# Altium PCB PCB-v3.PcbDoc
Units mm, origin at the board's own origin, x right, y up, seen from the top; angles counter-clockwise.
Board outline 31.7 x 33.1 mm, 2 copper layers (Top Layer, Bottom Layer); 47 components, 31 nets, 206 pads, 13 vias.
Unrouted connection lines stored in the file: 46.
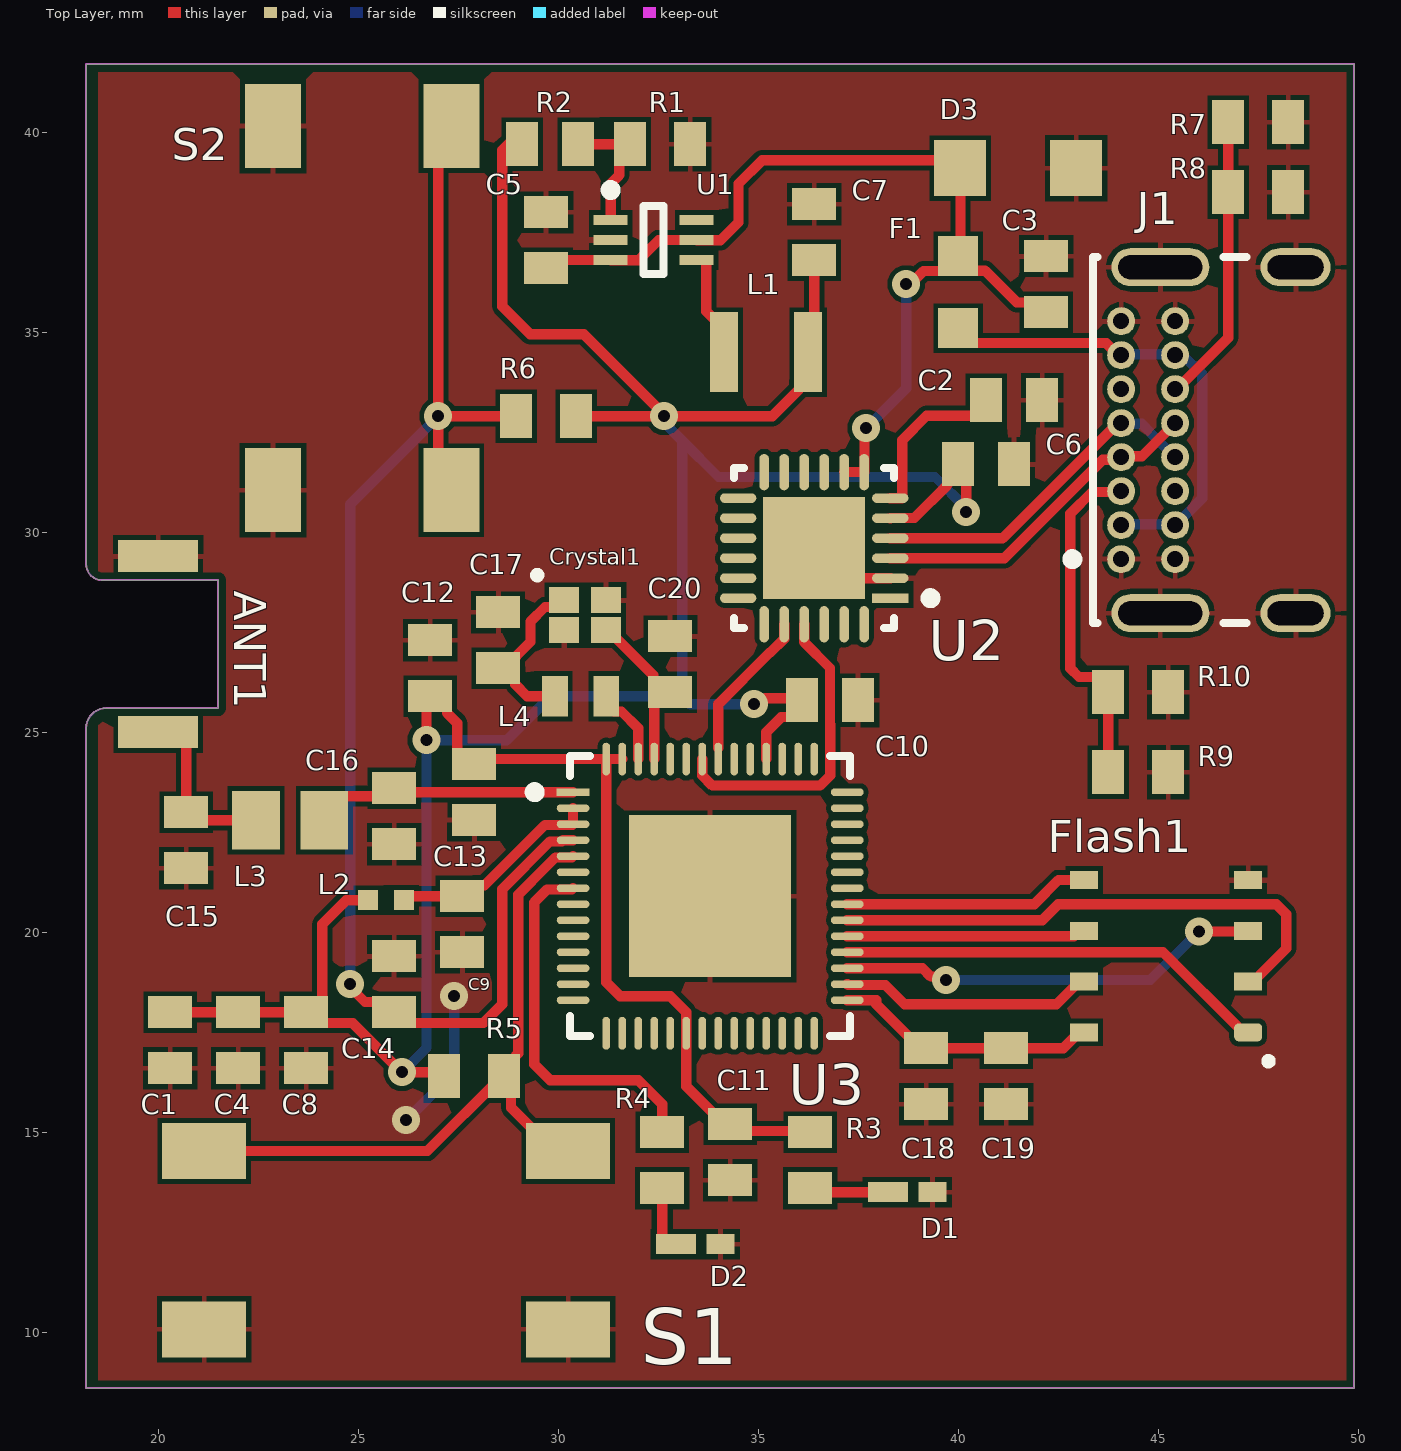
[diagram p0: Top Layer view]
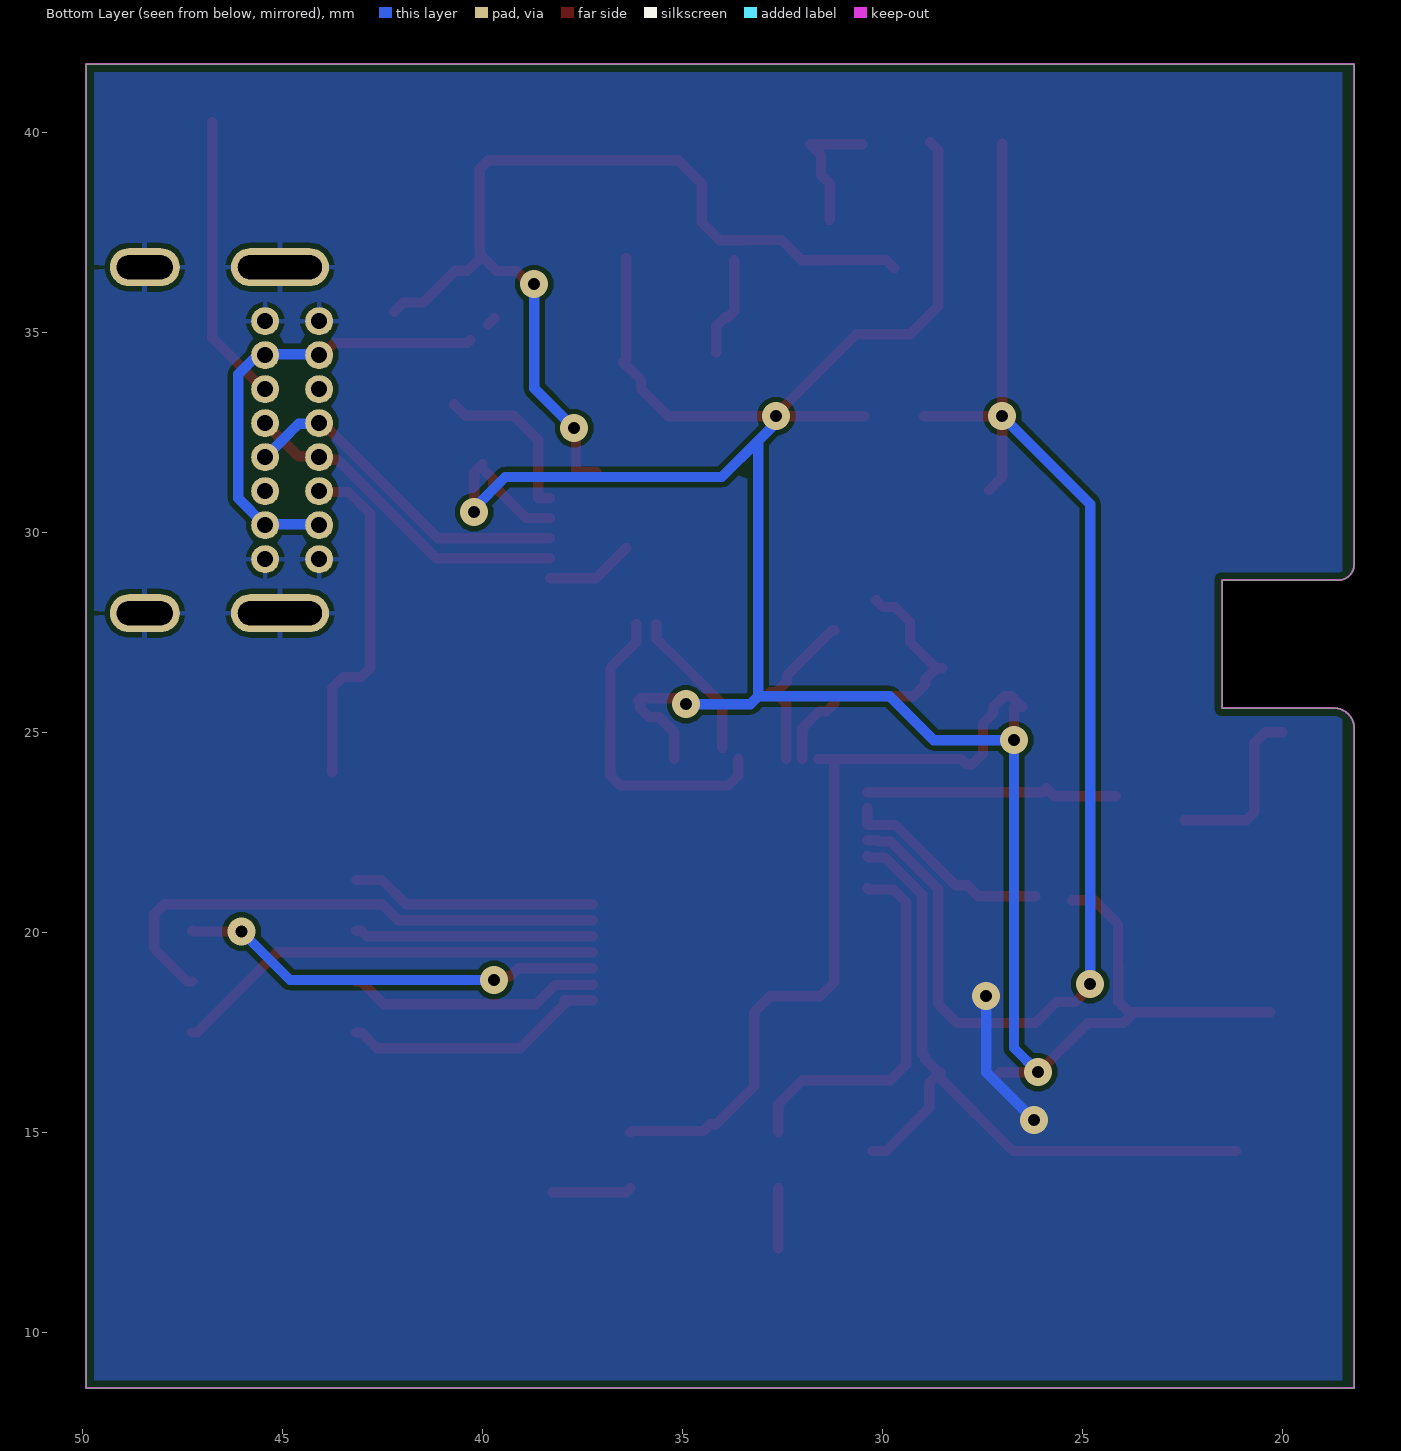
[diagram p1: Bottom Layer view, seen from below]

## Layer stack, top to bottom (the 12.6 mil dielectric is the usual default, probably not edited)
Top Solder: solder mask 0.0102, Solder Resist, Dk 3.5
Top Layer: signal copper 0.0356
Dielectric 1: dielectric 0.32, FR-4, Dk 4.8
Bottom Layer: signal copper 0.0356
Bottom Solder: solder mask 0.0102, Solder Resist, Dk 3.5

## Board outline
18.2,25.1 cw(c18.7,25.1) 18.7,25.6 21.5,25.6 21.5,28.8 18.6,28.8 cw(c18.6,29.2) 18.2,29.2 18.2,41.7 49.9,41.7 49.9,8.6 18.2,8.6

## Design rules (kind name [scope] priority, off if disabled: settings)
BoardOutlineClearance [All] p1: gap=0.2 ignorepadtopadclearanceinfootprint=FALSE
Clearance [All] p1: gap=0.127 ignorepadtopadclearanceinfootprint=TRUE except(0.254: Arc-Hole Track-Hole SMDPad-Hole THPad-Hole Via-Hole Fill-Hole Poly-Hole Region-Hole Text-Hole)
ComponentClearance [All] p1: gap=0.127 collisioncheckmode=3 verticalgap=0.127 showdistances=TRUE
DiffPairsRouting [All] p1: maxlimit=0.254 minlimit=0.127 mostfreqgap=0.127 toplayer_minwidth=0.127 toplayer_maxwidth=25.4 toplayer_prefwidth=0.127 bottomlayer_minwidth=0.127 bottomlayer_maxwidth=25.4 bottomlayer_prefwidth=0.127 maxuncoupledlength=12.7
Height [All] p1: minheight=0 maxheight=1816.048 prefheight=12.7
HoleSize [All] p1: absolutevalues=TRUE maxlimit=6.3 minlimit=0.3 maxpercent=80.000 minpercent=20.000
HoleToHoleClearance [All] p1: gap=0.254 allowstackedmicrovias=FALSE
MinimumAnnularRing [All] p1: minimumring=0.152
MinimumSolderMaskSliver [All] p1: minsoldermaskwidth=0.152
PlaneClearance [All] p1: clearance=0.127
PlaneConnect PlaneConnectPowerPads [InPadClass('PowerPads')] p1: planeconnectstyle=Direct reliefexpansion=0.508 reliefentries=4 reliefconductorwidth=0.254 reliefairgap=0.254
PlaneConnect [All] p2: pad.planeconnectstyle=Relief pad.reliefexpansion=0.3 pad.reliefentries=4 pad.reliefconductorwidth=0.127 pad.reliefairgap=0.127 via.planeconnectstyle=Direct via.reliefexpansion=0.3 via.reliefentries=4 via.reliefconductorwidth=0.127 via.reliefairgap=0.127
PolygonConnect PolygonConnectPowerPads [All vs (InPadClass('PowerPads'))] p1: connectstyle=Direct reliefconductorwidth=0.254 reliefentries=4 polygonreliefangle="90 Angle" airgapwidth=0.254
PolygonConnect [All] p2: thpad.connectstyle=Relief thpad.reliefconductorwidth=0.127 thpad.reliefentries=4 thpad.polygonreliefangle="90 Angle" thpad.airgapwidth=0.127 smdpad.connectstyle=Relief smdpad.reliefconductorwidth=0.127 smdpad.reliefentries=4 smdpad.polygonreliefangle="90 Angle" smdpad.airgapwidth=0.127 via.connectstyle=Direct via.reliefconductorwidth=0.127 via.reliefentries=4 via.polygonreliefangle="90 Angle" via.airgapwidth=0.127
RoutingVias [All] p1: holewidth=0.3 width=0.6 viastyle="Through Hole" minholewidth=0.3 minwidth=0.6 maxholewidth=0.6 maxwidth=6.6
SilkToSilkClearance [All] p1: silktosilkclearance=0.127
SilkToSolderMaskClearance [IsPad] p1: minsilkscreentomaskgap=0.127 clearancetoexposedcopper=TRUE
SolderMaskExpansion [All] p1: expansion=0.051 istentingtop=FALSE
SupplyNets "Schematic Supply Nets_4" [InNet('+3.3V')] p1: voltage=0.000
SupplyNets "Schematic Supply Nets_1" [InNet('GND')] p2: voltage=0.000
UnRoutedNet [All] p1: checkbadconnections=TRUE
Width Width_10mil [All] p1: maxlimit=25.4 minlimit=0.254 preferedwidth=0.254 minimp=50.000000 maximp=50.000000 favimp=50.000000
Width Width_6mil [All] p2: maxlimit=25.4 minlimit=0.152 preferedwidth=0.152 minimp=50.000000 maximp=50.000000 favimp=50.000000
Width Power_20mil [All] p3: maxlimit=25.4 minlimit=0.508 preferedwidth=0.508 minimp=50.000000 maximp=50.000000 favimp=50.000000
Width Power_12mil [All] p4: maxlimit=25.4 minlimit=0.305 preferedwidth=0.305 minimp=50.000000 maximp=50.000000 favimp=50.000000
Width Width_5mil [All] p5: maxlimit=25.4 minlimit=0.127 preferedwidth=0.127 minimp=50.000000 maximp=50.000000 favimp=50.000000
19 further rules are at their usual default settings.

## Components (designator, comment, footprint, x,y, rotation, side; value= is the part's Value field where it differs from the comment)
ANT1 "PCB_ANT" "Antenne // RFANT5220110A0T" 20,27.2 r90 top
C1 "10µF" CAP_General_0603 20.3,17.3 r90 top
C2 "1µF" CAP_General_0603 41.4,33.3 r0 top
C3 "10pF" CAP_General_0603 42.2,36.2 r270 top
C4 "1µF" CAP_General_0603 22,17.3 r90 top
C5 "4.7µF" CAP_General_0603 29.7,37.3 r270 top
C6 "1µF" CAP_General_0603 40.7,31.7 r0 top
C7 "1µF" CAP_General_0603 36.4,37.5 r270 top
C8 "0.1µF" CAP_General_0603 23.7,17.3 r90 top
C9 "0.1µF" CAP_General_0603 27.6,20.2 r90 top
C10 "0.1µF" CAP_General_0603 36.8,25.8 r0 top
C11 "0.1µF" CAP_General_0603 34.3,14.5 r90 top
C12 "1µF" CAP_General_0603 26.8,26.6 r270 top
C13 "10nF" CAP_General_0603 27.9,23.5 r90 top
C14 "0.1µF" CAP_General_0603 25.9,18.7 r270 top
C15 "1pF" CAP_General_0603 20.7,22.3 r90 top
C16 "1pF" CAP_General_0603 25.9,22.9 r90 top
C17 "10pF" CAP_General_0603 28.5,27.3 r90 top
C18 "0.1µF" CAP_General_0603 39.2,16.4 r90 top
C19 "10µF" CAP_General_0603 41.2,16.4 r90 top
C20 "10pF" CAP_General_0603 32.8,26.7 r90 top
Crystal1 "Crystal" "Crystal // ECS­400­8­47B2­CKM­TR" 30.675,27.925 r0 top
D1 "LED" "LED // KRDELPS1.22-UIVG-46-H3Q4-XX" 38.8,13.5 r0 top
D2 "LED" "LED // KRDELPS1.22-UIVG-46-H3Q4-XX" 33.5,12.2 r0 top
D3 "ESD diode 5V" "ESD diode 5V // SMF5.0A" 41.5,39.1 r0 top
F1 "Fuse" "Fuse // 0603L050SLYR" 40,36 r90 top
Flash1 "128 Mbit NOR Flash" "128 Mbit NOR Flash // AT25QF128A-MHB-T" 45.2,19.4 r180 top
J1 "USB4085-GF-A" "USB-C connector // USB4085-GF-A" 48.1,32.3 r90 top
L1 "1µH" "Inductor 1µH // MLP2520H1R0MT0S1" 35.2,34.5 r0 top
L2 "2nH" "Inductor 2nH // MLG1005S2N0BTD25" 25.7,20.8 r0 top
L3 "3.3nH" "Inductor 3.3nH // AIMC-0805-3N3" 23.3,22.8 r0 top
L4 "24nH" "Inductor 24 nH // 36501J24NJTDG" 30.56,25.9 r0 top
R1 "100K" RES_100K_0603 32.55,39.7 r180 top
R2 "453K" RES_453K_0603 29.8,39.7 r180 top
R3 "499R" RES_499R_0603 36.3,14.3 r270 top
R4 "499R" RES_499R_0603 32.6,14.3 r270 top
R5 "10K" RES_10K_0603_1 27.9,16.4 r0 top
R6 "10K" RES_10K_0603_1 29.7,32.9 r0 top
R7 "10K" RES_10K_0603_1 47.5,40.25 r180 top
R8 "10K" RES_10K_0603_1 47.5,38.5 r180 top
R9 "10K" RES_10K_0603_1 44.5,24 r180 top
R10 "10K" RES_10K_0603_1 44.5,26 r180 top
S1 "Drukknop" "Tactile Switches // FSM4JSMAATR" 25.7,12.3 r90 top
S2 "Drukknop" "Tactile Switches // FSM4JSMAATR" 25.1,35.6 r0 top
U1 "Convertor // 5.5V-3.3V" "CONVERTOR // TLV62569APDRLR" 32.388,37.304 r0 top
U2 "CP2102N-A02-GQFN24R" "USB Bridge // CP2102N-A02-GQFN24R" 36.4,29.6 r180 top
U3 "ESP32-S3R8" FP-ESP32-S3R8 33.8,20.9 r0 top

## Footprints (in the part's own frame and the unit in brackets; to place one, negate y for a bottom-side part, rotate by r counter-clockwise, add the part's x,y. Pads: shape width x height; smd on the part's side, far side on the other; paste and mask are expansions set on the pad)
"128 Mbit NOR Flash // AT25QF128A-MHB-T" [mm]
  rrect50% 0.7x0.45 smd: 1(-2.05,1.905)
  rect 0.7x0.45 smd: 2(-2.05,0.635) 3(-2.05,-0.635) 4(-2.05,-1.905) 5(2.05,-1.905) 6(2.05,-0.635) 7(2.05,0.635) 8(2.05,1.905)
  silkscreen extent -2.64,2.55 -2.48,2.71
"Antenne // RFANT5220110A0T" [mm]
  rect 0.8x2 smd: 1(-2.2,0) 2(2.2,0)
CAP_General_0603 [mm] "Chip Capacitor, 2-Leads, Body 1,60x0,80mm, IPC Medium Density"
  rect 0.8x1.1 smd: 1(-0.7,0) 2(0.7,0)
  body extent -0.85,-0.45 0.85,0.45, height 0.7
"CONVERTOR // TLV62569APDRLR" [mm] "SOT23, 6-Leads, Body 1,60x2,15mm, Pitch 0,50mm, IPC Medium Density"
  rect 0.85x0.25 smd mask+0.04: 1(-1.075,0.5) 2(-1.075,0) 3(-1.075,-0.5) 4(1.075,-0.5) 5(1.075,0) 6(1.075,0.5)
  silkscreen extent -1.2,-0.85 0.25,1.37, body extent -0.65,-0.85 0.65,0.85, height 0.6
"Crystal // ECS­400­8­47B2­CKM­TR" [mm] "40 MHz Crystal"
  rect 0.75x0.65 smd: 1(-0.525,0.375) 2(-0.525,-0.375) 3(0.525,-0.375) 4(0.525,0.375)
  silkscreen extent -1.28,0.92 -1.12,1.08
"ESD diode 5V // SMF5.0A" [mm]
  rect 1.3x1.4 smd: 1(-1.45,0) 2(1.45,0)
FP-ESP32-S3R8 [mm]
  rect 0.818x0.192 smd paste+0 mask+0: 1(-3.427,2.6)
  rrect100% 0.818x0.192 smd paste+0 mask+0: 2(-3.427,2.2) 3(-3.427,1.8) 4(-3.427,1.4) 5(-3.427,1) 6(-3.427,0.6) 7(-3.427,0.2) 8(-3.427,-0.2) 9(-3.427,-0.6) 10(-3.427,-1) 11(-3.427,-1.4) 12(-3.427,-1.8) 13(-3.427,-2.2) 14(-3.427,-2.6) 29(3.427,-2.6) 30(3.427,-2.2) 31(3.427,-1.8) 32(3.427,-1.4) 33(3.427,-1) 34(3.427,-0.6) 35(3.427,-0.2) 36(3.427,0.2) 37(3.427,0.6) 38(3.427,1) 39(3.427,1.4) 40(3.427,1.8) 41(3.427,2.2) 42(3.427,2.6)
  rrect100% 0.192x0.818 smd paste+0 mask+0: 15(-2.6,-3.427) 16(-2.2,-3.427) 17(-1.8,-3.427) 18(-1.4,-3.427) 19(-1,-3.427) 20(-0.6,-3.427) 21(-0.2,-3.427) 22(0.2,-3.427) 23(0.6,-3.427) 24(1,-3.427) 25(1.4,-3.427) 26(1.8,-3.427) 27(2.2,-3.427) 28(2.6,-3.427) 43(2.6,3.427) 44(2.2,3.427) 45(1.8,3.427) 46(1.4,3.427) 47(1,3.427) 48(0.6,3.427) 49(0.2,3.427) 50(-0.2,3.427) 51(-0.6,3.427) 52(-1,3.427) 53(-1.4,3.427) 54(-1.8,3.427) 55(-2.2,3.427) 56(-2.6,3.427)
  rect 4.05x4.05 smd paste-1000 mask+0: 57(0,0)
  silkscreen extent -4.51,-3.5 3.5,3.5, body extent -4.1,-4.09 4.07,4.09, height 0.25
"Fuse // 0603L050SLYR" [mm]
  rect 1x1 smd: 1(-0.9,0) 2(0.9,0)
"Inductor 1µH // MLP2520H1R0MT0S1" [mm]
  rect 0.7x2 smd: 1(-1.05,0) 2(1.05,0)
"Inductor 2nH // MLG1005S2N0BTD25" [mm]
  rect 0.5x0.5 smd: 1(-0.45,0) 2(0.45,0)
"Inductor 3.3nH // AIMC-0805-3N3" [mm] "Chip Inductor, 2-Leads, Body 2,00x1,25mm, IPC Medium Density"
  rect 1.19x1.47 smd: 1(-0.855,0) 2(0.855,0)
  body extent -1.1,-0.72 1.1,0.72, height 1.05
"Inductor 24 nH // 36501J24NJTDG" [mm]
  rect 0.64x1.02 smd: 1(-0.64,0) 2(0.64,0)
"LED // KRDELPS1.22-UIVG-46-H3Q4-XX" [mm]
  rect 1x0.5 smd mask+0.05: 1(-0.557,0)
  rect 0.7x0.5 smd mask+0.05: 2(0.557,0)
RES_10K_0603_1 [mm] "Chip Resistor, 2-Leads, Body 1,55x0,80mm, IPC Medium Density"
  rect 0.8x1.1 smd: 1(-0.75,0) 2(0.75,0)
  body extent -0.83,-0.45 0.82,0.45, height 0.55
RES_100K_0603 [mm] "Chip Resistor, 2-Leads, Body 1,60x0,80mm, IPC Medium Density"
  rect 0.8x1.1 smd: 1(-0.75,0) 2(0.75,0)
  body extent -0.9,-0.5 0.9,0.5, height 0.65
RES_453K_0603 [mm] "Chip Resistor, 2-Leads, Body 1,55x0,80mm, IPC Medium Density"
  rect 0.8x1.1 smd: 1(-0.7,0) 2(0.7,0)
  body extent -0.83,-0.45 0.82,0.45, height 0.55
RES_499R_0603 [mm] "Chip Resistor, 2-Leads, Body 1,55x0,85mm, IPC Medium Density"
  rect 0.8x1.1 smd: 1(-0.7,0) 2(0.7,0)
  body extent -0.8,-0.48 0.8,0.47, height 0.55
"Tactile Switches // FSM4JSMAATR" [mm]
  rect 1.4x2.1 smd: 1(2.23,4.55) 2(2.23,-4.55) 3(-2.23,4.55) 4(-2.23,-4.55)
"USB Bridge // CP2102N-A02-GQFN24R" [mm]
  rect 0.91x0.239 smd paste+0 mask+0: 1(-1.901,1.25)
  rrect100% 0.91x0.239 smd paste+0 mask+0: 2(-1.901,0.75) 3(-1.901,0.25) 4(-1.901,-0.25) 5(-1.901,-0.75) 6(-1.901,-1.25) 13(1.901,-1.25) 14(1.901,-0.75) 15(1.901,-0.25) 16(1.901,0.25) 17(1.901,0.75) 18(1.901,1.25)
  rrect100% 0.239x0.91 smd paste+0 mask+0: 7(-1.25,-1.901) 8(-0.75,-1.901) 9(-0.25,-1.901) 10(0.25,-1.901) 11(0.75,-1.901) 12(1.25,-1.901) 19(1.25,1.901) 20(0.75,1.901) 21(0.25,1.901) 22(-0.25,1.901) 23(-0.75,1.901) 24(-1.25,1.901)
  rect 2.55x2.55 smd paste-1000 mask+0: 25(0,0)
  silkscreen extent -3.03,-2 2,2, body extent -2.61,-2.61 2.61,2.61, height 0.25
"USB-C connector // USB4085-GF-A" [mm]
  rrect100% 0.95x2.45 hole 2.1 slot 0.6 at 0 deg paste-2539.97 mask+0: 1(-4.325,3.045) 2(4.325,3.045)
  rrect100% 0.95x1.75 hole 1.4 slot 0.6 at 0 deg paste-2539.97 mask+0: 3(-4.325,-0.335) 4(4.325,-0.335)
  round 0.7 hole 0.4 paste-2539.97 mask+0: A1(-2.975,4.025) A4(-2.125,4.025) A5(-1.275,4.025) A6(-0.425,4.025) A7(0.425,4.025) A8(1.275,4.025) A9(2.125,4.025) A12(2.975,4.025) B1(2.975,2.675) B4(2.125,2.675) B5(1.275,2.675) B6(0.425,2.675) B7(-0.425,2.675) B8(-1.275,2.675) B9(-2.125,2.675) B12(-2.975,2.675)
  silkscreen extent -4.57,0.89 4.57,5.37, body extent -4.87,-4.83 4.87,4.83, height 0.25

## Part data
ANT1: library part "Antenne // RFANT5220110A0T"
C1 C2 C3 C4 C5 C6 C7 C8 C9 C10 C11 C12 C13 C14 C15 C16 C17 C18 C19 C20: library part CAP_General_0603, "Capacitor SMD 0603 ?pF"
Crystal1: library part "Crystal // ECS­400­8­47B2­CKM­TR"
D1 D2: library part "LED // KRDELPS1.22-UIVG-46-H3Q4-XX"
D3: library part "ESD diode 5V // SMF5.0A"
F1: library part "Fuse // 0603L050SLYR"
Flash1: library part "128 Mbit NOR Flash // AT25QF128A-MHB-T"
J1: library part "USB-C connector // USB4085-GF-A", "CONN RCPT USB2.0 TYPE C 24POS RA"
L1: library part "Inductor 1µH // MLP2520H1R0MT0S1"
L2: library part "Inductor 2nH // MLG1005S2N0BTD25"
L3: library part "Inductor 3.3nH // AIMC-0805-3N3"
L4: library part "Inductor 24 nH // 36501J24NJTDG"
R1: library part RES_100K_0603, "Resistor SMD 0603 100K"
R2: library part RES_453K_0603, "Resistor SMD 0603 453K"
R3 R4: library part RES_499R_0603, "Resistor SMD 0603 499R"
R5 R6 R7 R8 R9 R10: library part RES_10K_0603_1, "Resistor SMD 0603 10K"
S1 S2: library part "Tactile Switches // FSM4JSMAATR"
U1: library part "Convertor // TLV62569APDRLR"
U2: library part "USB Bridge // CP2102N-A02-GQFN24R", "IC USB TO UART BRIDGE QFN24", Ambient Temperature Range High=85°C, Manufacturer Lifecycle Status="FULL PRODUCTION", Max Junction Temperature (Tj)=105°C, Max Supply Voltage=3.6V, Min Operating Temperature=-40°C, Min Supply Voltage=1.71V
U3: library part ESP32-S3, "ESP32-S3R8 RF System on a Chip - SoC SMD IC, Dual-Core MCU, Wi-Fi 2.4G BLE 5.0 Combo"

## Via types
v1: diameter 0.7, hole 0.3, Top Layer to Bottom Layer, 13 vias

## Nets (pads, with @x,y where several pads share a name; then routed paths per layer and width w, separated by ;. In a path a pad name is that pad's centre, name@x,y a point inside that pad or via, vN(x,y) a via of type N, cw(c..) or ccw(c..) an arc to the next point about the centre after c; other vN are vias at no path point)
+3.3V: C1.2 C4.2 C6.1 C7.2 C8.2 C10.1 C11.2 C12.2 C13.2 L1.2 L2.1 R2.2 R3.1 R5.1 R6.2 U2.5 U3.20 U3.46 U3.55 U3.56 | length 89.9
  Top Layer w0.254: C1.2 C4.2 C8.2 ; L2.1 24.7,20.8 24.102,20.202 24.102,19.202 24.1,19.2 24.1,18.273 23.827,18 C8.2 ; v1(26.704,24.8) 26.704,25.627 26.5,25.627 26.773,25.9 C12.2 26.95,25.9 27.223,25.627 27.223,25.477 27.477,25.223 27.477,24.473 27.75,24.2 C13.2 28.027,24.327 U3.56 ; R5.1 27.05,16.5 v1(26.1,16.5) 26.091,16.5 24.864,17.727 23.973,17.727 C8.2 ; R2.2@28.8,39.75 28.6,39.55 28.6,35.649 29.3,34.949 30.642,34.949 32.592,32.999 v1@32.592,32.971 ; R6.2 32.5,32.9 v1(32.65,32.9) 35.351,32.9 36.027,33.576 36.027,33.804 L1.2@36.473,34.25 ; U3.55 U3.56 ; v1(34.9,25.7) 35.021,25.7 35.171,25.85 C10.1@36.05,25.85 ; U3.46 35.2,25 35.577,25.377 35.827,25.377 36.05,25.6 C10.1@36.05,25.85 ; C10.1 C10.1@36.05,25.85 ; R3.1 36.273,15.027 34.473,15.027 C11.2 34.15,15.2 33.2,16.15 U3.20 33.2,18 32.8,18.4 31.549,18.4 31.2,18.749 U3.56 ; L1.2@36.4,34.323 36.4,34.546 C7.2 C7.2@36.4,36.85 ; U2.5 38.309,30.357 38.907,30.357 39.727,31.177 39.727,31.327 C6.1@39.9,31.5 ; C6.1 40.2,31.5 v1(40.2,30.5)
  Bottom Layer w0.254: v1(26.1,16.5) 26.704,17.104 v1(26.704,24.8) 28.71,24.8 29.81,25.9 33.1,25.9 ; v1@32.5,32.9 32.5,32.887 33.1,32.287 ; v1(34.9,25.7) 33.3,25.7 33.1,25.9 ; v1(40.2,30.5) 40.2,30.6 39.422,31.378 34.008,31.378 33.1,32.287 ; 33.1,25.9 33.1,32.287
+5V: C3.2 C5.2 D3.1 F1.2 U1.3 U1.5 U2.7 U2.8 | length 24.3
  Top Layer w0.254: C5.2 29.904,36.804 U1.3 ; U1.3@31.317,36.8 32.009,36.8 32.513,37.304 U1.5 ; U1.5@33.467,37.3 34.059,37.3 34.509,37.75 34.509,38.709 35.1,39.3 39.85,39.3 D3.1 ; U2.8 U2.7 37.657,31.509 37.657,32.557 v1(37.7,32.6) ; v1(38.7,36.2) 38.803,36.2 39.13,36.527 39.636,36.527 F1.2@40,36.891 ; D3.1@40.059,39.091 40.059,36.959 F1.2 40.365,36.535 40.674,36.535 41.464,35.745 41.964,35.745 C3.2@42.2,35.509
  Bottom Layer w0.254: v1(37.7,32.6) 38.7,33.6 v1(38.7,36.2)
GND: ANT1.2 C1.1 C2.2 C3.1 C4.1 C5.1 C6.2 C7.1 C8.1 C9.1 C10.2 C11.1 C12.1 C13.1 C14.1 C15.1 C16.1 C17.2 C18.1 C19.1 C20.2 Crystal1.2 Crystal1.4 D1.2 D2.2 D3.2 Flash1.4 J1.1 J1.2 J1.3 J1.4 J1.A1 J1.A12 J1.B1 J1.B12 R1.1 R7.1 R8.1 R9.1 R10.1 S1.3 S1.4 S2.3 S2.4 U1.2 U2.2 U2.25 U3.57 | length 5.9
  Top Layer w0.254: v1@27.3,18.4 v1(27.4,18.4) ; U2.25 37.15,28.85 U2.2
  Bottom Layer w0.254: v1(26.2,15.3) 27.4,16.5 v1(27.4,18.4)
NetANT1_1: ANT1.1 C15.2 L3.1 | length 4.4
  Top Layer w0.254: ANT1.1 20.427,25 20.7,24.727 C15.2 20.9,22.8 L3.1
NetC2_1: C2.1 U2.6 | length 4.2
  Top Layer w0.254: U2.6 38.593,30.85 38.6,30.857 38.6,32.3 39.21,32.91 40.427,32.91 40.7,33.183 C2.1@40.7,33.2
NetC9_2: C9.2 L2.2 U3.2 U3.3 | length 5.3
  Top Layer w0.254: L2.2@26.17,20.9 C9.2 27.873,21.173 28.16,21.173 29.668,22.681 30.354,22.681 U3.3 U3.2
NetC14_2: C14.2 R6.1 S2.1 S2.2 U3.4 | length 35.5
  Top Layer w0.254: v1(24.8,18.7) 24.8,18.624 25.172,18.253 25.647,18.253 26.173,17.727 28.127,17.727 28.6,18.2 28.6,21.074 29.795,22.269 30.091,22.269 30.122,22.3 U3.4 ; S2.1@27,39.72 v1(27,32.9) ; S2.2 27,31.38 v1(27,32.9) ; R6.1 v1(27,32.9)
  Bottom Layer w0.254: v1(24.8,18.7) 24.8,30.7 v1(27,32.9)
NetC16_2: C16.2 L3.2 U3.1 | length 6.3
  Top Layer w0.254: L3.2@24.155,23.4 25.7,23.4 C16.2 26,23.5 U3.1
NetC17_1: C17.1 Crystal1.1 L4.1 | length 4.3
  Top Layer w0.254: C17.1 C17.1@28.65,26.6 ; L4.1 29.219,25.9 28.923,26.196 28.923,26.327 C17.1@28.65,26.6 ; Crystal1.1 29.979,28.129 29.67,28.129 29.304,27.763 29.304,27.254 C17.1@28.65,26.6
NetC18_2: C18.2 C19.2 Flash1.8 U3.29 | length 6.6
  Top Layer w0.254: U3.29 37.95,18.3 37.95,18.2 39.05,17.1 C18.2 C19.2 42.63,17.1 43.025,17.495 Flash1.8
NetC20_1: C20.1 Crystal1.3 U3.53 | length 4.1
  Top Layer w0.254: Crystal1.3 31.25,27.55 32.377,26.423 32.377,26.273 C20.1@32.65,26 ; U3.53 32.4,25.727 32.673,26 C20.1
NetD1_1: D1.1 R3.2 | length 2
  Top Layer w0.254: R3.2 36.4,13.5 D1.1
NetD2_1: D2.1 R4.2 | length 1.5
  Top Layer w0.254: D2.1@32.6,12.1 R4.2
NetFlash1_1: Flash1.1 U3.32 | length 10.9
  Top Layer w0.254: U3.32 45.12,19.5 47.125,17.495 Flash1.1
NetFlash1_2: Flash1.2 U3.34 | length 13.4
  Top Layer w0.254: U3.34 42.1,20.3 42.5,20.7 47.951,20.7 48.2,20.451 48.2,19.59 47.375,18.765 Flash1.2
NetFlash1_3: Flash1.3 U3.31 | length 10.7
  Top Layer w0.254: U3.31 39.106,19.1 39.317,18.889 39.615,18.889 v1(39.7,18.804) ; v1(46.018,20.018) 47.233,20.018 Flash1.3
  Bottom Layer w0.254: v1(39.7,18.804) 44.804,18.804 v1(46.018,20.018)
NetFlash1_5: Flash1.5 U3.35 | length 6.2
  Top Layer w0.254: U3.35 41.9,20.7 42.505,21.305 Flash1.5
NetFlash1_6: Flash1.6 U3.33 | length 6
  Top Layer w0.254: U3.33 42.89,19.9 43.025,20.035 Flash1.6
NetFlash1_7: Flash1.7 U3.30 | length 6.4
  Top Layer w0.254: U3.30 37.246,18.681 38.175,18.681 38.656,18.2 42.46,18.2 43.025,18.765 Flash1.7
NetJ1_A5: J1.A5 R9.2 R10.2 | length 8.6
  Top Layer w0.254: R9.2 43.75,26.107 43.477,26.38 43.02,26.38 42.8,26.6 42.8,30.461 43.344,31.005 44.075,31.005 J1.A5@44.085,30.995
NetJ1_A6: J1.A6 J1.B6 U2.3 | length 8.5
  Top Layer w0.254: U2.3 41.15,29.35 43.612,31.812 43.987,31.812 44.075,31.9 44.596,31.9 45.421,32.725 J1.B6
NetJ1_A7: J1.A7 J1.B7 U2.4 | length 8.6
  Top Layer w0.254: U2.4 41.111,29.85 43.961,32.7 J1.A7@44.09,32.7
  Bottom Layer w0.254: J1.A7@44.14,32.75 44.178,32.712 44.588,32.712 44.821,32.479 44.821,32.475 45.421,31.875 J1.B7
NetJ1_B5: J1.B5 R7.2 R8.2 | length 7.2
  Top Layer w0.254: J1.B5@45.49,33.6 46.75,34.86 R8.2 R7.2
NetL1_1: L1.1 U1.4 | length 2.5
  Top Layer w0.254: U1.4@33.7,36.802 33.7,35.522 33.849,35.373 33.927,35.373 34.15,35.15 L1.1
NetL4_2: L4.2 U3.54 | length 2
  Top Layer w0.254: L4.2 31.2,25.71 31.393,25.517 31.583,25.517 32,25.1 U3.54
NetR1_2: R1.2 R2.1 U1.1 | length 3.4
  Top Layer w0.254: R2.1 R1.2 31.527,39.427 31.527,38.927 31.313,38.713 U1.1
NetR4_1: R4.1 U3.7 | length 9.5
  Top Layer w0.254: U3.7 30.342,21.069 29.724,21.069 29.4,20.745 29.4,16.7 29.8,16.3 32,16.3 32.6,15.7 R4.1
NetR5_2: R5.2 S1.1 S1.2 U3.5 | length 17.6
  Top Layer w0.254: S1.1 26.73,14.53 28.55,16.35 R5.2@28.55,16.5 ; S1.2 29.9,14.53 28.823,15.607 28.823,16.227 28.625,16.425 R5.2@28.55,16.5 ; U3.5 30.342,21.869 29.934,21.869 29.71,21.645 29,20.935 29,16.972 28.923,16.895 28.923,16.823 28.6,16.5 R5.2@28.55,16.5
NetU2_20: U2.20 U3.49 | length 3.8
  Top Layer w0.254: U3.49@34,24.609 34,25.7 35.29,26.99 35.305,26.99 35.65,27.335 U2.20
NetU2_21: U2.21 U3.50 | length 7.9
  Top Layer w0.254: U3.50 33.6,23.919 33.855,23.664 36.545,23.664 36.8,23.919 36.8,25.191 36.796,25.195 36.796,26.605 36.15,27.251 U2.21
VBus: F1.1 J1.A4 J1.A9 J1.B4 J1.B9 | length 11.7
  Top Layer w0.254: F1.1@39.7,35.35 F1.1@39.85,35.2 ; F1.1@40.3,34.8 40.373,34.727 43.703,34.727 44.005,34.425 J1.A9
  Bottom Layer w0.254: J1.A4@44.14,30.2 J1.B9@45.49,30.2 ; J1.A9@44.14,34.45 45.597,34.45 46.1,33.947 46.1,30.846 45.429,30.175 J1.B9
pads on no net: J1.A8 J1.B8 U1.6 U2.1 U2.9 U2.10 U2.11 U2.12 U2.13 U2.14 U2.15 U2.16 U2.17 U2.18 U2.19 U2.22 U2.23 U2.24 U3.6 U3.8 U3.9 U3.10 U3.11 U3.12 U3.13 U3.14 U3.15 U3.16 U3.17 U3.18 U3.19 U3.21 U3.22 U3.23 U3.24 U3.25 U3.26 U3.27 U3.28 U3.36 U3.37 U3.38 U3.39 U3.40 U3.41 U3.42 U3.43 U3.44 U3.45 U3.47 U3.48 U3.51 U3.52

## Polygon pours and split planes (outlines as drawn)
GND on Top Layer "GND_L01_P004" (solid, remove dead copper, pour order 4): 18.5,41.5 50,41.5 50,8.8 18.5,8.8
GND on Bottom Layer "GND_L02_P005" (solid, remove dead copper, pour order 5): 49.8,8.8 18.5,8.8 18.5,41.5 49.8,41.5

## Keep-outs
Keep-Out Layer:
  the board outline again, w0.05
